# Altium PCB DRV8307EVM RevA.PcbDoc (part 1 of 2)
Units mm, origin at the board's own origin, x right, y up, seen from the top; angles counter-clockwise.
Board outline 87.73 x 75 mm, 2 copper layers (Top Layer, Bottom Layer), stack 1.575 mm thick; 84 components, 57 nets, 289 pads, 360 vias.
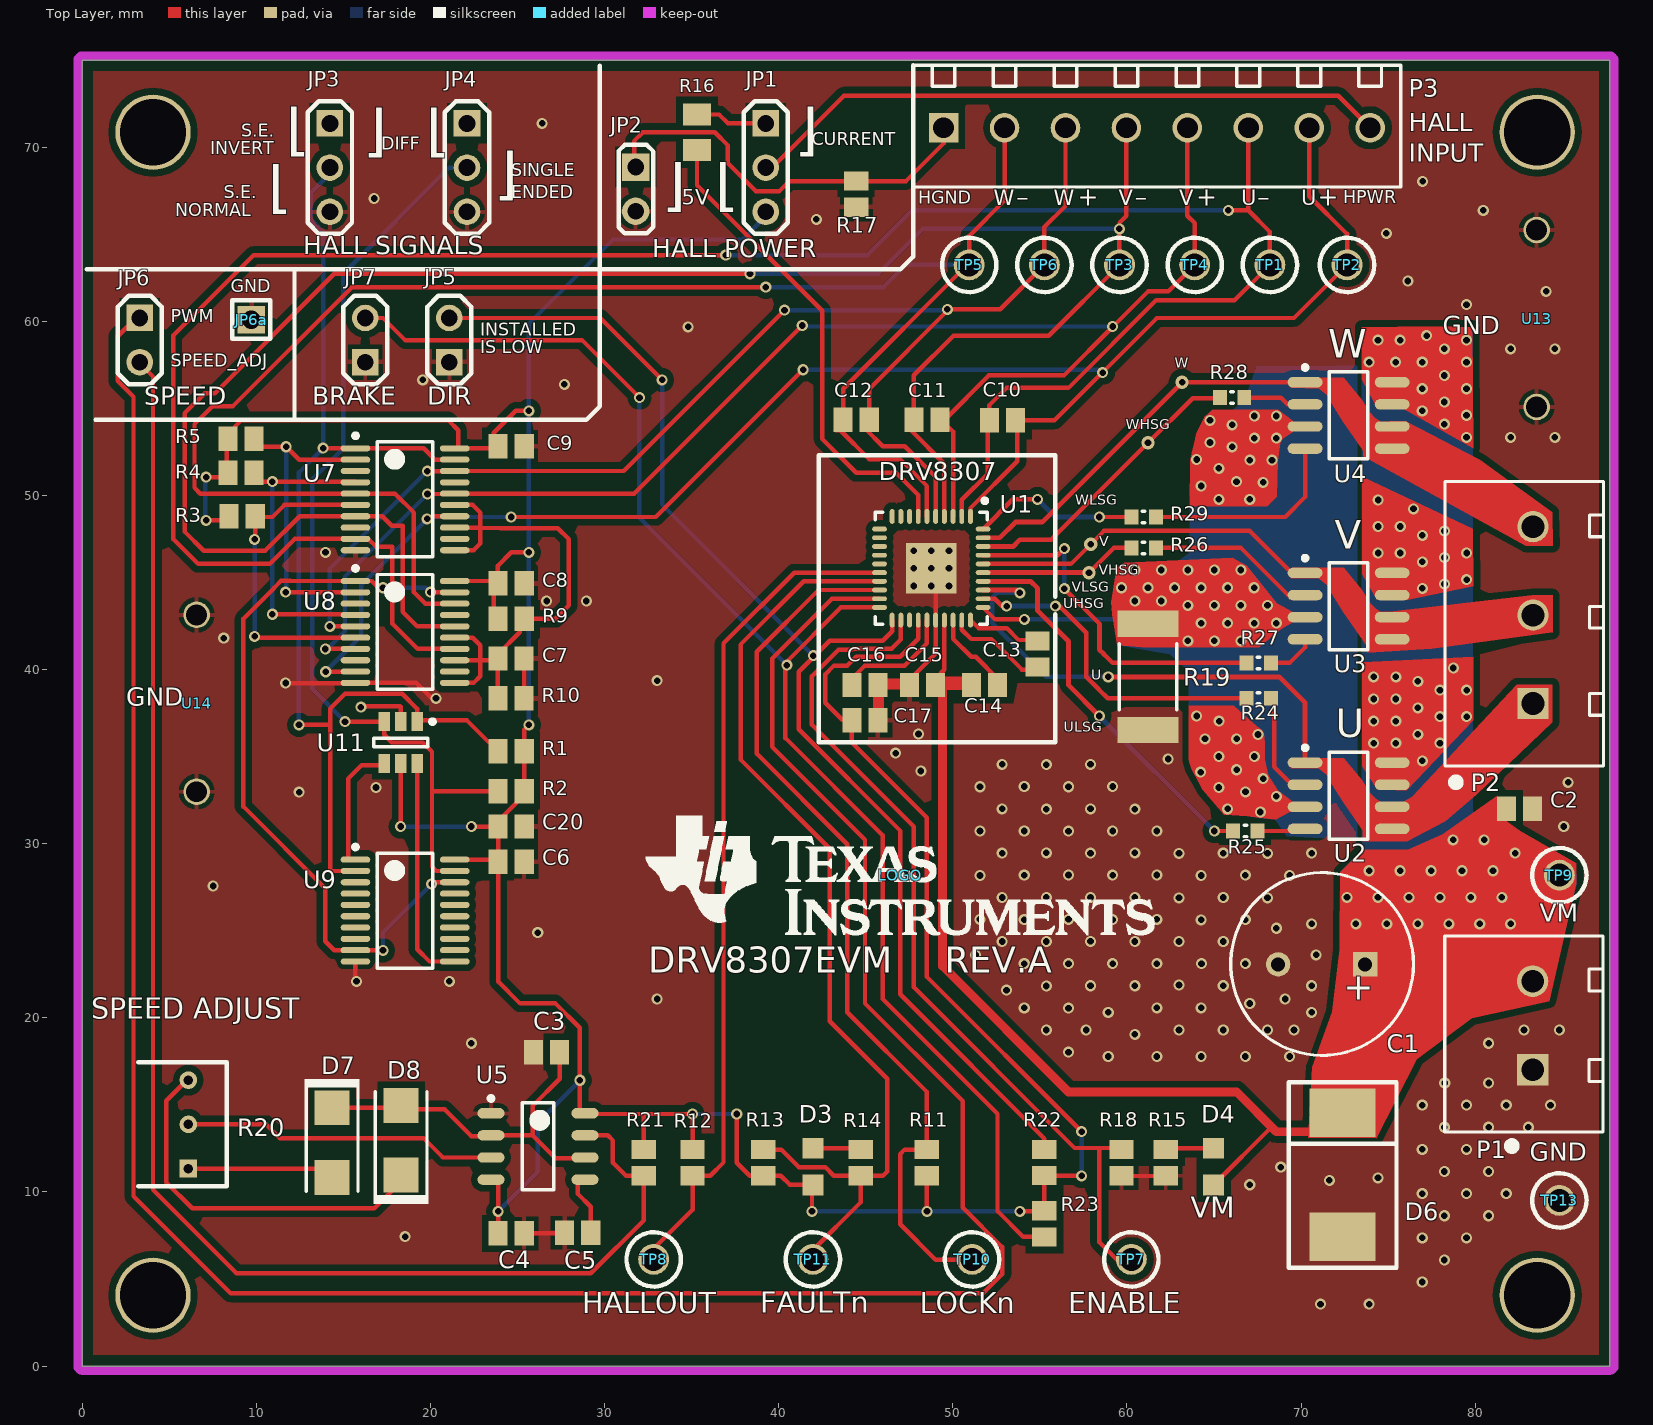
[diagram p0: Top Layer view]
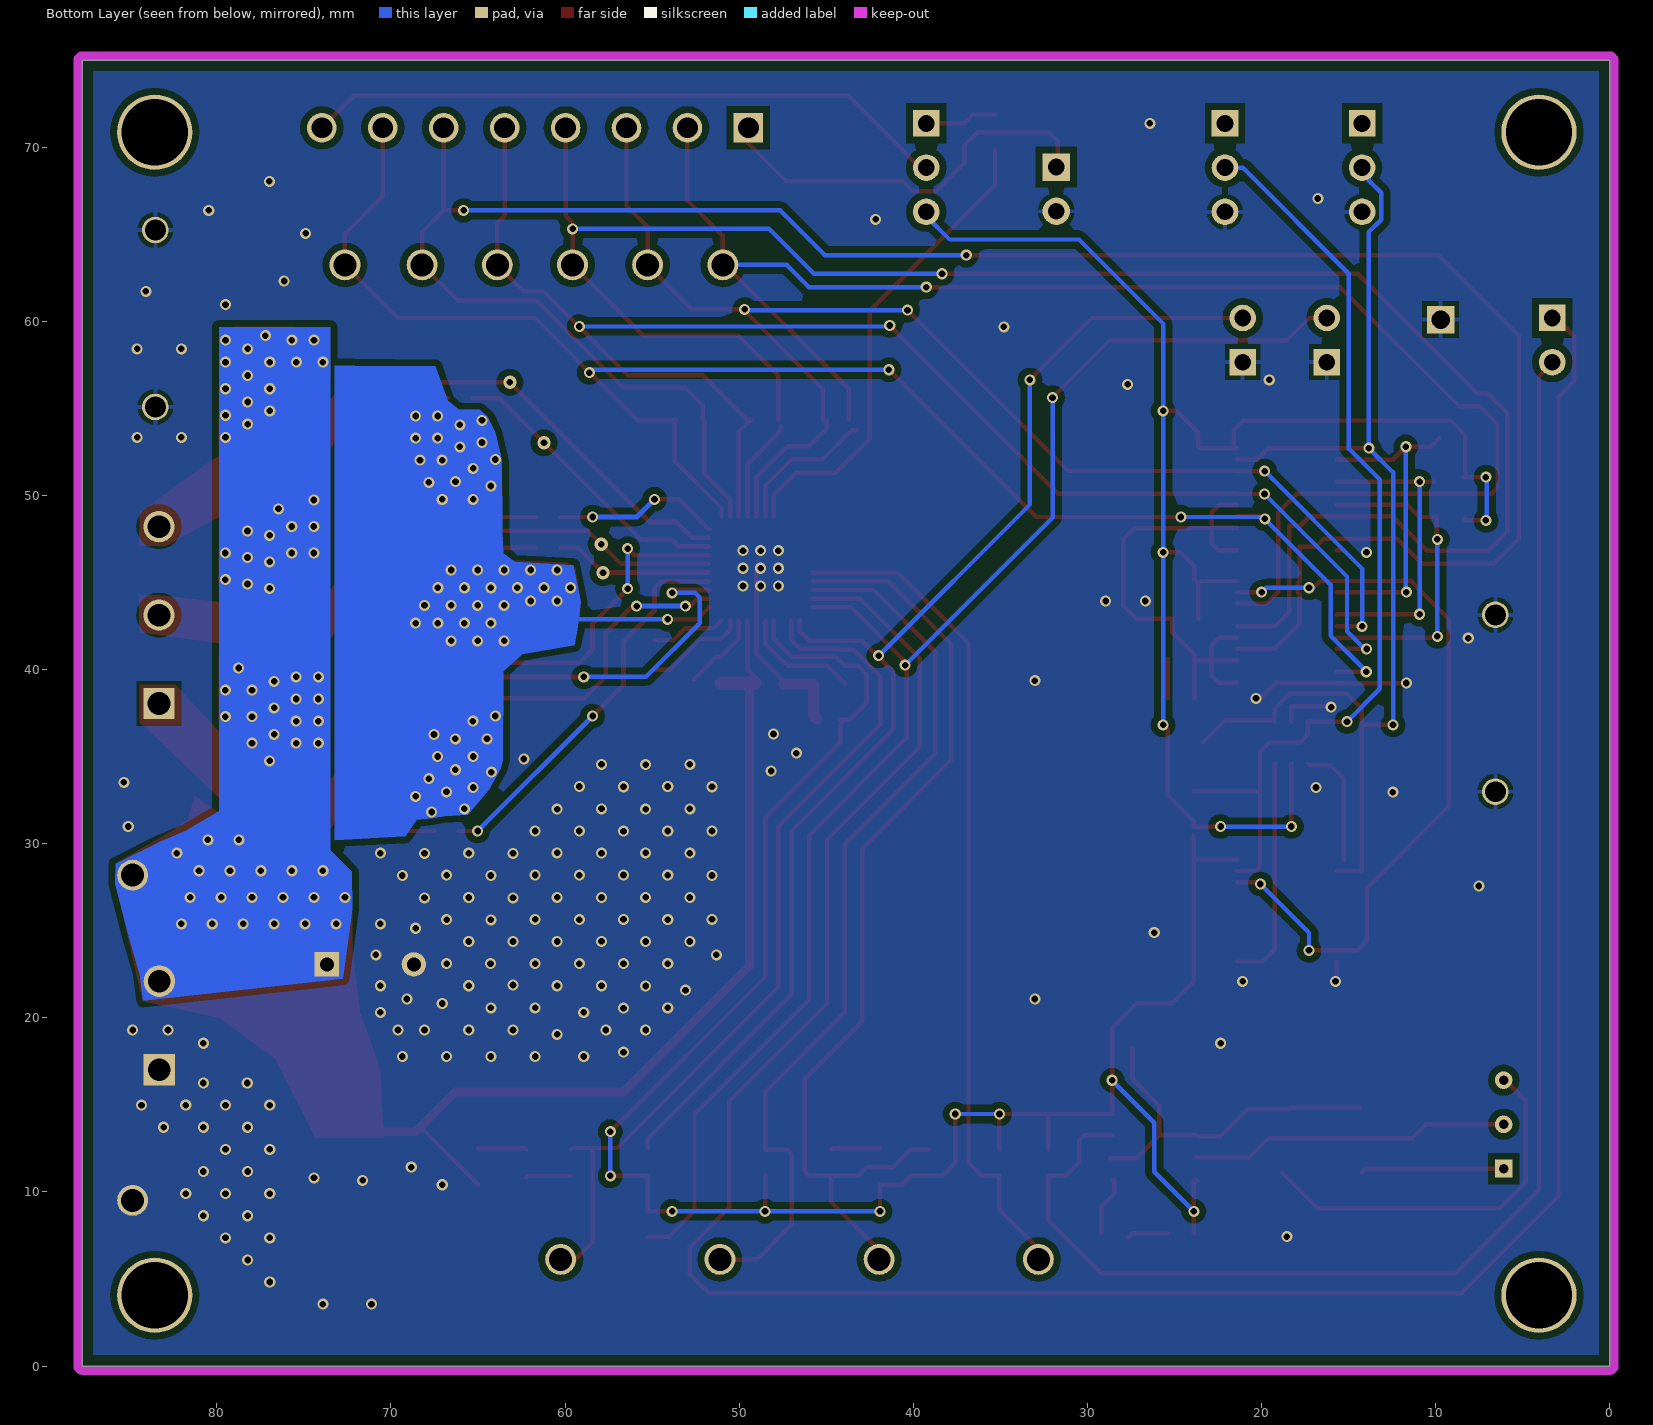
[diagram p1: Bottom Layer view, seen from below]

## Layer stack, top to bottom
Top Layer: signal copper 0.0356
Dielectric: core 1.5037, FR-4, Dk 4.8
Bottom Layer: signal copper 0.0356

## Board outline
0,0 0,75 87.732,75 87.732,0

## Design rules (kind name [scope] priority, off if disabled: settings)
AcuteAngle [All] p1: minimum=1.50000000000000E+0001 checktracksonly=FALSE
AssemblyTestPointUsage [All] p1: valid=2
Clearance Clearance_BoardEdge_MountingHoles [OnCopper and InComponentClass('Mounting Holes') vs IsKeepOut] p1: gap=1.016
Clearance Clearance_BoardEdge_Poly [OnCopper and InPoly vs IsKeepOut] p2: gap=0.635
Clearance Clearance_BoardEdge [OnCopper and Not InComponentClass('Logo') and not InComponentClass('FiducialMark') and not InRegion(1000,500,4000,800) and Not IsKeepout vs IsKeepOut] p3: gap=1.905
Clearance Clearance_Poly [InPolygon] p4: gap=0.381
Clearance [All] p5: gap=0.203
ComponentClearance ComponentClearance_Logo [InComponentClass('Logo')] p1: gap=1.27 collisioncheckmode=3 verticalgap=0.254 showdistances=FALSE
ComponentClearance ComponentClearance_ScrewToNut [(HasFootprint('NY PMS 440 0025 PH')) vs (HasFootprint('Keystone_1902C'))] p2: gap=0.127 collisioncheckmode=3 verticalgap=0.254 showdistances=FALSE
ComponentClearance ComponentClearance_MountingHoles [InComponentClass('Mounting Holes')] p3: gap=6.35 collisioncheckmode=3 verticalgap=2540 showdistances=FALSE
ComponentClearance ComponentClearance_SmallPassives [HasFootprint('0201*') or HasFootprint('0402*') or HasFootprint('0508') or HasFootprint('0603*') or HasFootprint('0612') or HasFootprint('0805*') or HasFootprint('0815*') or HasFootprint('0830*') or HasFootprint('1206*') or HasFootprint('1210*') or HasFootprint('1808*') or HasFootprint('1812*') or HasFootprint('1825*') or HasFootprint('2010*') or HasFootprint('2220*') or HasFootprint('2225*') or HasFootprint('2512*') or HasFootprint('2728*') or HasFootprint('3518*') vs HasFootprint('0201*') or HasFootprint('0402*') or HasFootprint('0508') or HasFootprint('0603*') or HasFootprint('0612') or HasFootprint('0805*') or HasFootprint('0815*') or HasFootprint('0830*') or HasFootprint('1206*') or HasFootprint('1210*') or HasFootprint('1808*') or HasFootprint('1812*') or HasFootprint('1825*') or HasFootprint('2010*') or HasFootprint('2220*') or HasFootprint('2225*') or HasFootprint('2512*') or HasFootprint('2728*') or HasFootprint('3518*')] p4: gap=0.508 collisioncheckmode=3 verticalgap=0.254 showdistances=FALSE
ComponentClearance ComponentClearance_THtoSMT [IsThruComponent vs IsSMTComponent] p5: gap=1.38 collisioncheckmode=3 verticalgap=0.762 showdistances=FALSE
ComponentClearance ComponentClearance_THtoTH [IsThruComponent vs IsThruComponent] p6: gap=0 collisioncheckmode=3 verticalgap=0.762 showdistances=FALSE
ComponentClearance [All] p7: gap=1.016 collisioncheckmode=3 verticalgap=0.254 showdistances=FALSE
DiffPairsRouting [All] p1: maxlimit=2.54 minlimit=0.254 mostfreqgap=0.254 maxuncoupledlength=25.4
FabricationTestPointUsage TestPointUsage [All] p1: valid=2 allowmultiple=FALSE
FabricationTestpoint Testpoint [All] p1: side=3 testpointundercomponent=TRUE minsize=1.016 maxsize=2.54 preferedsize=1.524 minholesize=0 maxholesize=1.016 preferedholesize=0.813 testpointgrid=0.025 allowsidetop=TRUE allowsidebottom=TRUE usegrid=TRUE gridtolerance=0
FanoutControl Fanout_LCC [IsLCC] p1: bgadir=Out bgaviamode=Centered fanoutstyle=Auto fanoutdirection=Alternating viagrid=0.025 // Fanout_LCC (Default Rule)
FanoutControl Fanout_BGA [IsBGA] p2: bgadir=Out bgaviamode=Centered fanoutstyle=Auto fanoutdirection=Alternating viagrid=0.025 // Fanout_BGA (Default Rule)
FanoutControl Fanout_Default [All] p4: bgadir=Out bgaviamode=Centered fanoutstyle=Auto fanoutdirection=Alternating viagrid=0.025 // Fanout_Default (Default Rule)
FanoutControl Fanout_Small [(CompPinCount < 5)] p5: bgadir=Out bgaviamode=Centered fanoutstyle=Auto fanoutdirection=OutThenIn viagrid=0.025 // Fanout_Small (Default Rule)
HoleSize [All] p1: absolutevalues=TRUE maxlimit=6.375 minlimit=0.203 maxpercent=80.000 minpercent=20.000
MinimumAnnularRing [All] p1: minimumring=0.127
MinimumSolderMaskSliver MinimumSolderMaskSliver_Logo [InComponentClass('Logo') vs InComponentClass('Logo')] p1: minsoldermaskwidth=0.018
MinimumSolderMaskSliver [All] p2: minsoldermaskwidth=0.076
PlaneConnect [All] p1: planeconnectstyle=Relief reliefexpansion=0.254 reliefentries=4 reliefconductorwidth=0.254 reliefairgap=0.254
PolygonConnect PolygonConnect_1 [IsNamedPolygon('Top GND plane') or IsNamedPolygon('Bottom GND plane') vs not ( InComponent('U1') or InComponent('C1') or       InComponent('C2') or InComponent('P1') or       InComponent('D6') or InComponent('R19') or       InComponent('TP13') or   InComponent('C3') or       InComponent('U11') or       IsStitchingVia or IsVia)] p1: connectstyle=Relief reliefconductorwidth=0.254 reliefentries=4 polygonreliefangle="90 Angle" airgapwidth=0.254
PolygonConnect [All] p2: connectstyle=Direct reliefconductorwidth=0.254 reliefentries=4 polygonreliefangle="90 Angle" airgapwidth=0.254
RoutingVias [All] p1: holewidth=0.406 width=0.864 viastyle="Through Hole" minholewidth=0.203 minwidth=0.635 maxholewidth=1.016 maxwidth=1.651
SMDToCorner [All] p1: distance=0
SilkToSilkClearance [All] p1: silktosilkclearance=0.076
SilkscreenOverComponentPads [All] p1: minsilkscreentomaskgap=0.051
SolderMaskExpansion [All] p1: expansion=0.076
Width [All] p1: maxlimit=2.54 minlimit=0.152 preferedwidth=0.254 checkconnectedcopper=TRUE
14 further rules are at their usual default settings.

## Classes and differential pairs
component class Logo: LOGO

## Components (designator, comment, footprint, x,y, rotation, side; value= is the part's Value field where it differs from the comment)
C1 "220uF" UVZ1J221MPD_fp 71.374,23.114 r180 top
C2 "06031C272JAT2A" 0805L 82.55,32.004 r0 top
C3 "GRM155R61A103KA01D" 0805L 26.67,18.034 r0 top
C4 "C1005X5R1A104K" 0805L 24.638,7.62 r180 top
C5 "GRM155R61A103KA01D" 0805L 28.454,7.662 r180 top
C6 "Cap" 0805L 24.638,28.956 r180 top
C7 "" 0805L 24.626,40.64 r0 top
C8 "Cap" 0805L 24.638,44.958 r180 top
C9 "Cap" 0805L 24.638,52.832 r180 top
C10 "C0805C104K5RACTU" 0805L 52.851,54.319 r180 top
C11 "C0805C104K5RACTU" 0805L 48.514,54.356 r180 top
C12 "C0805C104K5RACTU" 0805L 44.45,54.356 r180 top
C13 "C0805C104K5RACTU" 0805L 54.864,40.894 r90 top
C14 "C0805C104K5RACTU" 0805L 51.816,39.116 r0 top
C15 "C0805C104K5RACTU" 0805L 48.26,39.116 r180 top
C16 "C0805C104K5RACTU" 0805L 44.958,39.116 r180 top
C17 "C0805C104K5RACTU" 0805L 44.958,37.084 r180 top
C20 "" 0805L 24.638,30.988 r0 top
D3 "LTST-C170KRKT" LED_LTST-C170 41.964,11.459 r90 top
D4 "LTST-C171GKT" LED_LTST-C171 64.979,11.459 r90 top
D6 "1.5SMC33" SMC-W 72.385,7.433 r90 top
D7 "MBRA210LT3G" SMA 14.349,12.838 r270 top
D8 "MBRA210LT3G" SMA 18.313,12.971 r90 top
JP1 "JUMPER_3X100MIL" HDR100_1X3 39.255,71.374 r270 top
JP2 "JUMPER_2X100MIL" "2PIN HEADER" 30.568,70.016 r270 top
JP3 "JUMPER_3X100MIL" HDR100_1X3 14.224,71.374 r270 top
JP4 "JUMPER_3X100MIL" HDR100_1X3 22.098,71.374 r270 top
JP5 "" HDR100_1X2 21.082,57.658 r90 top
JP6 "" HDR100_1X2 3.302,60.198 r270 top
JP6a "PartNumber" "1x1 Header" 10.922,58.928 r90 top
JP7 "" HDR100_1X2 16.256,57.658 r90 top
LOGO "Texas Instruments" TI_Stacked_Overlay_Medium 46.99,28.194 r0 top
P1 "OSTTA024163" On-Shore_OSTTA024163 82.804,19.064 r90 top
P2 "OSTTA034163" On-Shore_OSTTA034163 82.823,42.632 r90 top
P3 "OSTTE080161" On-Shore_OSTTE080161 61.722,71.12 r0 top
R1 "" 0805L 24.638,35.306 r0 top
R2 "" 0805L 24.638,33.02 r0 top
R3 "" 0805L 9.184,48.819 r180 top
R4 "" 0805L 9.124,51.308 r180 top
R5 "" 0805L 9.124,53.269 r180 top
R9 "" 0805L 24.638,42.926 r180 top
R10 "RT0805BRD0710KL" 0805L 24.626,38.354 r180 top
R11 "30K" 0805l 48.514,11.684 r270 top
R12 "15K" 0805L 35.052,11.684 r90 top
R13 "30K" 0805L 39.116,11.684 r270 top
R14 "3K" 0805L 44.704,11.684 r90 top
R15 "Res1" 0805L 62.23,11.684 r90 top
R16 "ERJ-6GEYJ202V" 0805_HV 35.306,70.866 r90 top
R17 "CRCW0805180RJNEA" 0805L 44.45,67.31 r270 top
R18 "" 0805L 59.69,11.684 r90 top
R19 "PartNumber" 2512M 61.214,39.584 r90 top
R20 "3352T-1-502LF" 3352_Trimmer_Pot 6.096,13.886 r90 top
R21 "CRCW040210K0JNED" 0805L 32.258,11.684 r90 top
R22 "" 0805L 55.258,11.696 r270 top
R23 "" 0805L 55.258,8.168 r90 top
R24 "RC0603FR-07240RL" 0603L 67.564,38.354 r0 top
R25 "RC0603FR-07240RL" 0603L 66.802,30.734 r0 top
R26 "RC0603FR-07240RL" 0603L 60.96,46.99 r0 top
R27 "RC0603FR-07240RL" 0603L 67.564,40.386 r0 top
R28 "RC0603FR-07240RL" 0603L 66.04,55.626 r0 top
R29 "RC0603FR-07240RL" 0603L 60.96,48.768 r0 top
TP1 "TP-LOOP-ORANGE" "TEST POINT 0.052" 68.212,63.246 r0 top
TP2 "TP-LOOP-ORANGE" "TEST POINT 0.052" 72.644,63.246 r0 top
TP3 "TP-LOOP-ORANGE" "TEST POINT 0.052" 59.576,63.246 r0 top
TP4 "TP-LOOP-ORANGE" "TEST POINT 0.052" 63.894,63.246 r0 top
TP5 "TP-LOOP-ORANGE" "TEST POINT 0.052" 50.94,63.246 r0 top
TP6 "TP-LOOP-ORANGE" "TEST POINT 0.052" 55.258,63.246 r0 top
TP7 "TP-LOOP-ORANGE" "TEST POINT 0.052" 60.252,6.129 r0 top
TP8 "TP-LOOP-ORANGE" "TEST POINT 0.052" 32.82,6.129 r0 top
TP9 "TP-LOOP-ORANGE" "TEST POINT 0.052" 84.836,28.194 r0 top
TP10 "TP-LOOP-BLACK" "TEST POINT 0.052" 51.108,6.129 r0 top
TP11 "TP-LOOP-ORANGE" "TEST POINT 0.052" 41.964,6.129 r0 top
TP13 "TP-LOOP-BLACK" "TEST POINT 0.052" 84.836,9.517 r0 top
U1 "DRV8307" RHA0040A 48.766,45.822 r270 top
U2 "CSD88537ND" SO-8_N 72.734,32.757 r0 top
U3 "CSD88537ND" SO-8_N 72.734,43.648 r0 top
U4 "CSD88537ND" SO-8_N 72.734,54.601 r0 top
U5 "TLC555" SOIC127P600X175-8N 26.178,12.616 r0 top
U7 "SN74CBT3244CPW" PW0020A_N 18.542,49.784 r0 top
U8 "SN74CBT3244CPW" PW0020A_N 18.542,42.164 r0 top
U9 "SN74CBT3244CPW" PW0020A_N 18.542,26.162 r0 top
U11 "SN74LVC2G14DBVR" DBV0006A_N 18.288,35.814 r270 top
U13 "" GND_Bridge 81.534,53.086 r0 top
U14 "" GND_Bridge 4.572,30.988 r0 top

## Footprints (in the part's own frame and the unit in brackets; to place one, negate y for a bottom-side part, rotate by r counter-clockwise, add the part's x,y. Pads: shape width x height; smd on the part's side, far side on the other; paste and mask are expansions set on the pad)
"1x1 Header" [mil]
  rect 62x62 hole 42: 1(46.41,47.38)
  silkscreen extent 3,5 90,90
"2PIN HEADER" [mil]
  rect 62x62 hole 38: 1(45.31,48.03)
  round 62 hole 38: 2(145.31,48.03)
  silkscreen extent -5,9 195,88
0603L [mm] "0603 from SM-752 data"
  rect 0.8x0.85 smd: 1(-0.7,0) 2(0.7,0)
  silkscreen extent -0.07,-0.33 0.07,0.33, body extent -0.87,-0.47 0.87,0.47, height 0.85
0805_HV [mil] "0805 with 30mil clearance between pads"
  rect 50x63 smd: 1(-40,0) 2(40,0)
  body extent -43,-29 43,29, height 43
0805L [mm] "0805 from SM-752 data"
  rect 1.1x1.4 smd: 1(-0.75,0) 2(0.75,0)
  body extent -1.1,-0.72 1.1,0.72, height 1.1
0805l [mm] "0805 from SM-752 data"
  rect 1.1x1.4 smd: 1(-0.75,0) 2(0.75,0)
  body extent -1.1,-0.72 1.1,0.72, height 1.1
2512M [mm] "Chip Resistor, Body 6.3x3.2mm, IPC Low Density"
  rect 1.5x3.5 smd: 1(-3.05,0) 2(3.05,0)
  silkscreen extent -1.9,-1.65 1.9,1.65, body extent -3.22,-1.67 3.22,1.67, height 0.71
3352_Trimmer_Pot [mil]
  rect 40x40 hole 21.65: 1(-100,0)
  round 40 hole 21.65: 2(0,0) 3(100,0)
  silkscreen extent -140,-87 140,113
DBV0006A_N [mm] "SOT23, 6-Leads, Body 2.9x1.6mm, Pitch 0.95mm, Lead Span 2.8mm, IPC Medium Density"
  rect 1.1x0.65 smd: 1(-1.2,0.95) 2(-1.2,0) 3(-1.2,-0.95) 4(1.2,-0.95) 5(1.2,0) 6(1.2,0.95)
  silkscreen extent -1.32,-1.55 0.25,1.95, body extent -1.42,-1.46 1.42,1.46, height 1.11
GND_Bridge [mm] "Test Pin for GND"
  round 1.524 hole 1.2: 1(2,12.16) 2(2,2)
HDR100_1X2 [mil]
  rect 60x60 hole 38: 1(0,0)
  round 60 hole 38: 2(100,0)
  silkscreen extent -50,-50 150,50
HDR100_1X3 [mil]
  rect 60x60 hole 38: 1(0,0)
  round 60 hole 38: 2(100,0) 3(200,0)
  silkscreen extent -50,-50 250,50
LED_LTST-C170 [mm] "LITE-ON"
  rect 1.2x1.2 smd: 1(-1.05,0) 2(1.05,0)
  body extent -1.05,-0.67 1.05,0.67, height 1.1
LED_LTST-C171 [mm] "LITE-ON"
  rect 1.2x1.2 smd: 1(-1.05,0) 2(1.05,0)
  body extent -1.05,-0.67 1.05,0.67, height 0.8
On-Shore_OSTTA024163 [mm] "TERM BLOCK 2x1, 5.08mm, TH"
  rect 1.8x1.8 hole 1.3: 1(-2.04,-0.5)
  round 1.8 hole 1.3 paste+0: 2(3.04,-0.5)
  silkscreen extent -6.53,-4.55 5.63,4.55, body extent -5.68,-4.6 5.68,4.6, height 13
On-Shore_OSTTA034163 [mm] "TERM BLOCK 3x1, 5.08mm, TH"
  rect 1.8x1.8 hole 1.3: 1(-4.58,-0.5)
  round 1.8 hole 1.3 paste+0: 2(0.5,-0.5) 3(5.58,-0.5)
  silkscreen extent -9.2,-4.55 8.17,4.55, body extent -8.22,-4.6 8.22,4.6, height 13
On-Shore_OSTTE080161 [mm] "Term Blk 8x1"
  rect 1.7x1.7 hole 1.2: 1(-12.25,0)
  round 1.7 hole 1.2: 2(-8.75,0) 3(-5.25,0) 4(-1.75,0) 5(1.75,0) 6(5.25,0) 7(8.75,0) 8(12.25,0)
  silkscreen extent -14,-3.4 14,3.6, body extent -14,-3.4 14,3.6, height 8.4
PW0020A_N [mm] "TSOP, 20-Leads, Body 6.5x4.4mm, Pitch 0.65mm, IPC Medium Density"
  oval 1.7x0.35 smd: 1(-2.85,2.925) 2(-2.85,2.275) 3(-2.85,1.625) 4(-2.85,0.975) 5(-2.85,0.325) 6(-2.85,-0.325) 7(-2.85,-0.975) 8(-2.85,-1.625) 9(-2.85,-2.275) 10(-2.85,-2.925) 11(2.85,-2.925) 12(2.85,-2.275) 13(2.85,-1.625) 14(2.85,-0.975) 15(2.85,-0.325) 16(2.85,0.325) 17(2.85,0.975) 18(2.85,1.625) 19(2.85,2.275) 20(2.85,2.925)
  silkscreen extent -2.97,-3.3 1.6,3.77, body extent -2.25,-3.3 2.25,3.3, height 1.2
RHA0040A [mm] "QFN, 40-Leads, Body 6x6mm, Pitch 0.5mm, Thermal Pad 2.9x2.9mm, TI Recommended"
  oval 0.85x0.28 smd paste-0.025 mask+0.07: 1(-2.975,2.25) 2(-2.975,1.75) 3(-2.975,1.25) 4(-2.975,0.75) 5(-2.975,0.25) 6(-2.975,-0.25) 7(-2.975,-0.75) 8(-2.975,-1.25) 9(-2.975,-1.75) 10(-2.975,-2.25) 21(2.975,-2.25) 22(2.975,-1.75) 23(2.975,-1.25) 24(2.975,-0.75) 25(2.975,-0.25) 26(2.975,0.25) 27(2.975,0.75) 28(2.975,1.25) 29(2.975,1.75) 30(2.975,2.25)
  oval 0.28x0.85 smd paste-0.025 mask+0.07: 11(-2.25,-2.975) 12(-1.75,-2.975) 13(-1.25,-2.975) 14(-0.75,-2.975) 15(-0.25,-2.975) 16(0.25,-2.975) 17(0.75,-2.975) 18(1.25,-2.975) 19(1.75,-2.975) 20(2.25,-2.975) 31(2.25,2.975) 32(1.75,2.975) 33(1.25,2.975) 34(0.75,2.975) 35(0.25,2.975) 36(-0.25,2.975) 37(-0.75,2.975) 38(-1.25,2.975) 39(-1.75,2.975) 40(-2.25,2.975)
  rect 2.9x2.9 smd paste-2.45 mask+0.07: 41(0,0)
  silkscreen extent -4,-3.22 3.22,3.22, body extent -3.08,-3.08 3.08,3.08, height 1
SMA [mm] "Molded Diode, 2-Leads, Body 4.3x2.6mm, IPC Medium Density, based on OnSemi component dimensions and land pattern"
  rect 2x2 smd: 1(-2,0) 2(2,0)
  silkscreen extent -3.66,-1.57 2.79,1.57, body extent -2.6,-1.3 2.6,1.3, height 2.42
SMC-W [mil]
  rect 110x150 smd: 1(0,0) 2(280,0)
  silkscreen extent -70,-122 349,122
SO-8_N [mm] "SOIC, 8-Leads, Body 4.9x3.9mm, Pitch 1.27mm, IPC Medium Density"
  oval 2x0.6 smd: 1(-2.5,1.905) 2(-2.5,0.635) 3(-2.5,-0.635) 4(-2.5,-1.905) 5(2.5,-1.905) 6(2.5,-0.635) 7(2.5,0.635) 8(2.5,1.905)
  silkscreen extent -2.62,-2.5 1.1,2.88, body extent -2,-2.5 2,2.5, height 1.75
SOIC127P600X175-8N [mm] "SOIC, 8-Leads, Body 5.0x4.0mm (max), Pitch 1.27mm, IPC Medium Density"
  oval 1.55x0.6 smd: 1(-2.7,1.905) 2(-2.7,0.635) 3(-2.7,-0.635) 4(-2.7,-1.905) 5(2.7,-1.905) 6(2.7,-0.635) 7(2.7,0.635) 8(2.7,1.905)
  silkscreen extent -2.82,-2.5 0.9,2.88, body extent -3.01,-2.51 3,2.49, height 1.75
"TEST POINT 0.052" [mil] "Glass Beaded Test Point"
  round 70 hole 52: 1(0,0)
  silkscreen extent -61,-61 62,61
TI_Stacked_Overlay_Medium [mm]
  silkscreen extent -14.62,-3.44 14.62,3.42
UVZ1J221MPD_fp [mm] "220uF footprint"
  rect 1.4x1.4 hole 0.8: 1(-2.31,0.045)
  round 1.4 hole 0.8: 2(2.69,0.045)
  silkscreen extent -5.09,-5.23 5.41,5.27, body extent -5.02,-5.2 5.43,5.29, height 27.01

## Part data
C1: library part UVZ1J221MPD
C2: "CAP, CERM, 2700pF, 100V, +/-5%, X7R, 0603"
C3 C5: "CAP, CERM, 0.01uF, 10V, +/-10%, X5R, 0402"
C4: "CAP, CERM, 0.1uF, 10V, +/-10%, X5R, 0402"
C6 C8 C9: "Capacitor"
C7 C20: library part Cap, "Capacitor"
C10 C11 C12 C13 C14 C15 C16 C17: "CAP, CERM, 0.1uF, 50V, +/-10%, X7R, 0805"
D3: "LED, Red, SMD"
D4: "LED, Green, SMD"
D6: library part "D Schottky", "Schottky Diode"
D7 D8: "Diode, Schottky, 10V, 2A, SMA"
JP1 JP3 JP4: "Header, Male 3-pin, 100mil spacing,"
JP2: "Header, Male 2-pin, 100mil spacing,"
JP5 JP6 JP7: library part JUMPER_2X100MIL, "Header, Male 2-pin, 100mil spacing,"
JP6a: library part "1x1 Header", "1x1 Header"
LOGO: library part TI_Logo, "Texas Instrument Corporate Signature"
P1: "Terminal Block, 2x1, 5.08mm, TH"
P2: "Terminal Block, 3x1, 5.08 mm, TH"
P3: "Terminal Block, 8x1, 3.5mm, TH"
R1 R2 R3 R4 R5 R9 R11 R12 R13 R14 R18 R22 R23: library part Res1, "Resistor"
R10: "RES, 10.0k ohm, 0.1%, 0.125W, 0805"
R15: "Resistor"
R16: "RES, 2.0k ohm, 5%, 0.125W, 0805"
R17: "RES, 180 ohm, 5%, 0.125W, 0805"
R19: library part CSRN2512FK30L0, "RES, 0.03 ohm, 1%, 2W, 2512"
R20: library part POT_3352P, "Potentiometer, 3/8 Cermet, SingleTurn, Flat"
R21: "RES, 10k ohm, 5%, 0.063W, 0402"
R24 R25 R26 R27 R28 R29: "RES, 240 ohm, 1%, 0.1W, 0603"
TP1 TP2 TP3 TP4 TP5 TP6 TP7 TP8 TP9 TP10 TP11 TP13: library part "TEST POINT", "Glass Beaded Test Point"
U1: library part DRV8308
U2 U3 U4: library part FDS8949, "MOSFET N-CH DUAL 30V 3.5A SOP8"
U5: "IC OSC MONO TIMING 2.1MHZ 8-SOIC"
U11: library part SN74LVC2G14IDBVRQ1, "DUAL SCHMITT-TRIGGER INVERTER, DBV0006A"
U13 U14: library part GND_Bridge

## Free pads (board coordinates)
  round 4.318 hole 3.81: 0(4.064,4.064) 0(4.064,70.866) 0(83.566,4.064) 0(83.566,70.866)

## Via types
v1: diameter 0.635, hole 0.381, Top Layer to Bottom Layer, tented both sides, 350 vias
v2: diameter 0.635, hole 0.381, Top Layer to Bottom Layer, tented bottom, 5 vias
v3: diameter 0.762, hole 0.381, Top Layer to Bottom Layer, tented bottom, 4 vias
v4: diameter 0.635/0.635 (per signal layer), hole 0.381, Top Layer to Bottom Layer, tented both sides, 1 vias

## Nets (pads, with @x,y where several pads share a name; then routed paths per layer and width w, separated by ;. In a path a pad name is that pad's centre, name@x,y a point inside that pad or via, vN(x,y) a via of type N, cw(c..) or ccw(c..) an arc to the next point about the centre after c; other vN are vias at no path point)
2V: C7.1 R9.1 R10.2 U7.11 U7.13 U7.15 U8.11 U8.13 U8.15 | length 31.5
  Top Layer w0.254: U8.11@21.392,39.239 22.475,39.239 22.86,39.624 22.86,40.539 ; U8.13@21.392,40.539 22.86,40.539 ; U8.15@21.392,41.839 22.423,41.839 22.86,41.402 22.86,40.539 ; U7.11@21.392,46.859 22.475,46.859 22.86,47.244 22.86,48.133 ; U7.13@21.392,48.159 22.834,48.159 22.86,48.133 ; U7.15@21.392,49.459 22.423,49.459 22.86,49.022 22.86,48.133 ; R10.2@23.876,38.354 C7.1@23.876,40.64 ; 22.86,40.539 23.775,40.539 C7.1@23.876,40.64 ; 22.86,48.133 24.003,48.133 24.016,48.12 27.318,48.12 27.94,47.498 27.94,43.688 27.178,42.926 25.134,42.926 25.134,42.152 23.876,40.894 C7.1@23.876,40.64
BRAKE: JP7.2 R23.1 U1.20 | length 83.1
  Top Layer w0.254: JP7.2@16.256,60.198 17.272,60.198 18.542,58.928 28.702,58.928 v1(32.004,55.626) ; U1.20@45.791,43.572 43.572,43.572 40.386,40.386 40.386,36.068 45.974,30.48 45.974,21.082 52.566,14.49 52.566,8.902 54.05,7.418 R23.1@55.258,7.418
  Bottom Layer w0.254: v1@31.995,55.626 31.995,48.738 v1(40.47,40.262)
CP1: C13.2 U1.30 | length 4.3
  Top Layer w0.254: U1.30@51.016,42.847 51.477,42.386 53.092,42.386 53.773,41.704 C13.2@54.87,41.704
CP2: C13.1 U1.29 | length 5.9
  Top Layer w0.254: U1.29@50.516,42.847 50.516,42.294 51.052,41.758 52.218,41.758 53.972,40.004 C13.1@54.87,40.004
DIR: JP5.2 R22.1 U1.21 | length 73.3
  Top Layer w0.254: JP5.2@21.082,60.198 29.747,60.198 v1(33.303,56.642) ; U1.21@46.516,42.847 46.516,42.198 45.974,41.656 44.069,41.656 42.926,41.656 41.148,39.878 41.148,36.576 46.99,30.734 46.99,21.352 ; 46.974,21.352 55.258,13.068 R22.1@55.258,12.533
  Bottom Layer w0.254: v1(33.303,56.642) 33.303,49.487 v1(41.989,40.801)
ENABLE#: R18.2 TP7.1 U1.22 | length 50.3
  Top Layer w0.254: U1.22@47.016,42.847 47.016,41.733 46.482,41.199 44.258,41.199 44.207,41.148 43.434,41.148 41.91,39.624 41.91,36.83 47.752,30.988 47.752,21.767 56.993,12.526 59.598,12.526 R18.2@59.69,12.434 ; 58.42,12.434 58.42,7.112 TP7.1@59.69,5.842
FAULTN: R13.1 R14.1 TP11.1 U1.17 | length 57
  Top Layer w0.254: R13.1@39.116,12.434 40.144,12.434 41.148,11.43 42.672,11.43 43.168,10.934 R14.1@44.704,10.934 ; TP11.1@41.964,6.129 41.964,6.658 44.704,9.398 R14.1@44.704,10.934 ; U1.17@45.791,45.072 41.445,45.072 37.81,41.438 37.81,34.834 42.926,29.718 42.926,19.812 46.228,16.51 46.228,11.176 45.986,10.934 R14.1@44.704,10.934
GND: C1.2 C2.2 C3.1 C4.1 C5.2 C6.1 C7.2 C8.1 C9.1 C15.2 C16.1 C17.1 C20.2 D6.1 JP2.2 JP3.3 JP4.3 JP5.1 JP6a.1 JP7.1 P1.1 R10.1 R15.1 R17.2 R18.1 R19.1 TP13.1 U1.26 U1.41 U5.1 U7.10 U8.10 U9.10 U11.2 U13.1 U13.2 U14.1 U14.2 | length 31.7
  Top Layer w0.254: v1(11.684,39.23) 15.683,39.23 U8.10@15.692,39.239 19.181,39.239 20.066,38.354 v1(20.32,38.354) ; U7.10@15.279,46.859 U7.10@15.692,46.859 ; U9.10@15.692,23.237 15.692,22.154 v1(15.748,22.098) ; v1(16.002,37.846) 16.05,37.894 18.252,37.894 18.288,37.858 U11.2@18.288,37.014 ; R10.1@25.376,38.354 C7.2@25.376,40.64 ; C4.1@25.388,7.62 27.432,7.62 C5.2@27.686,7.366 ; C15.2@47.458,39.363 49.016,40.921 U1.26@49.016,42.847 U1.41@49.016,45.572 ; R18.1@59.69,10.918 62.146,10.918 R15.1@62.23,10.834
  Top Layer w0.635: C17.1@45.552,37.152 45.72,37.321 45.72,39.184 C15.2@47.458,39.184
  other v1: 71.12,3.556 73.914,3.556 76.962,4.826 78.232,6.096 76.962,7.366 79.502,7.366 18.542,7.438 78.232,8.636 80.772,8.636 76.962,9.906 79.502,9.906 81.788,9.906 67.056,10.414 71.628,10.668 74.422,10.807 78.232,11.176 80.772,11.176 68.834,11.43 76.962,12.446 79.502,12.446 78.232,13.716 80.772,13.716 83.058,13.716 76.962,14.986 79.502,14.986 81.788,14.986 84.328,14.986 78.254,16.256 80.772,16.256 58.928,17.78 61.722,17.78 64.262,17.78 66.802,17.78 69.342,17.78 56.642,18.034 22.352,18.542 80.772,18.542 60.452,19.05 55.372,19.304 57.658,19.304 62.992,19.304 65.532,19.304 68.072,19.304 69.596,19.304 82.804,19.304 84.836,19.304 58.928,20.32 70.612,20.32 56.642,20.56 54.102,20.574 61.722,20.574 64.262,20.574 67.056,20.828 33.02,21.082 69.088,21.082 53.086,21.59 55.372,21.83 57.912,21.844 60.452,21.844 65.532,21.844 70.612,21.844 62.992,21.886 21.082,22.098 54.102,23.114 56.642,23.114 59.182,23.114 61.722,23.114 64.284,23.114 66.802,23.114 51.308,23.622 70.866,23.622 52.832,24.384 55.372,24.384 60.452,24.384 62.992,24.384 65.532,24.384 57.912,24.398 26.162,24.892 68.58,25.146 70.612,25.4 54.102,25.64 59.182,25.64 64.262,25.626 66.802,25.64 51.562,25.654 56.642,25.654 61.722,25.654 52.832,26.91 57.912,26.91 62.992,26.896 65.532,26.91 68.072,26.896 55.372,26.924 60.452,26.924 7.522,27.57 51.562,28.18 64.262,28.18 69.342,28.18 54.102,28.194 59.182,28.194 66.802,28.194 56.642,28.208 61.722,28.208 62.992,29.45 68.072,29.45 52.832,29.464 57.912,29.464 65.532,29.464 70.612,29.464 55.372,29.478 60.452,29.478 56.642,30.72 51.562,30.734 54.102,30.734 59.182,30.734 61.722,30.734 85.09,30.988 55.372,31.99 60.452,31.99 52.832,32.004 57.912,32.004 12.457,32.964 16.872,33.234 51.562,33.274 56.642,33.274 54.102,33.288 59.182,33.288 85.344,33.528 48.163,34.18 55.372,34.544 52.832,34.558 57.912,34.558 62.367,34.866 46.715,35.208 48.027,36.301 33.02,39.37 8.127,41.809 26.67,43.942 28.956,43.942 47.75,44.806 48.766,44.806 49.782,44.806 47.75,45.822 48.766,45.822 49.782,45.822 13.97,46.736 47.75,46.838 48.766,46.838 49.782,46.838 82.042,53.34 84.582,53.34 27.686,56.388 19.558,56.642 82.042,58.42 84.582,58.42 34.798,59.69 79.502,60.96 84.074,61.722 76.132,62.321 74.903,65.056 42.164,65.86 80.465,66.378 16.764,67.056 76.984,68.041 26.416,71.374
HALLOUT: R12.1 TP8.1 U1.16 | length 48.2
  Top Layer w0.254: TP8.1@33.02,6.096 33.02,6.95 35.052,8.982 R12.1@35.052,10.934 36.068,10.934 36.83,11.696 36.83,41.508 40.894,45.572 U1.16@45.791,45.572
HGND: JP2.1 P3.1 R17.1 | length 23.9
  Top Layer w0.254: JP2.1@31.696,68.445 31.696,70.358 32.204,70.866 36.322,70.866 37.084,70.104 37.084,69.088 38.684,67.488 40.043,67.488 40.615,68.06 R17.1@44.45,68.06 47.312,68.06 49.472,70.22 P3.1@49.472,71.12
HPWR: JP1.2 P3.8 | length 37.7
  Top Layer w0.254: JP1.2@38.862,68.58 39.37,68.58 43.746,72.956 72.136,72.956 P3.8@73.972,71.12
HU+: C10.1 P3.7 TP2.1 U1.1 U7.14 U8.9 | length 95
  Top Layer w0.254: v1(13.986,39.877) 15.68,39.877 U8.9@15.692,39.889 ; v1(19.812,48.657) 19.99,48.657 20.142,48.809 U7.14@21.392,48.809 ; v1(24.638,48.768) 32.945,48.768 v1(41.401,57.224) ; U1.1@51.016,48.797 51.016,49.284 53.701,51.969 C10.1@53.701,54.319 ; C10.1@53.601,54.319 C10.1@53.701,54.319 ; P3.7@70.472,71.12 70.472,67.196 72.644,65.024 TP2.1@72.644,63.246 69.596,60.198 61.722,60.198 55.843,54.319 C10.1@53.701,54.319
  Bottom Layer w0.254: 14.22,40.136 16.035,41.95 16.035,44.88 v1(19.812,48.657) 19.923,48.768 v1(24.638,48.768) ; v1(41.401,57.224) 58.444,57.224 v1(58.609,57.059) ; TP2.1@72.276,63.246 TP2.1@72.53,63.246
HU-: C10.2 P3.6 TP1.1 U1.2 U7.9 U8.14 | length 133.8
  Top Layer w0.254: 16.872,47.068 16.431,47.509 U7.9@15.692,47.509 12.203,47.509 10.766,46.072 6.657,46.072 5.231,47.498 5.231,59.195 9.84,63.804 v1@36.974,63.804 ; 16.879,47.062 17.815,47.062 17.815,45.077 17.92,44.972 17.92,44.436 17.815,44.331 17.815,42.637 19.263,41.189 U8.14@21.392,41.189 ; U1.2@50.516,48.797 50.516,49.754 52.001,51.239 C10.2@52.001,54.219 ; C10.2@52.101,54.319 52.101,55.195 53.086,56.179 56.642,56.179 61.677,61.214 ; 61.722,61.214 66.18,61.214 TP1.1@68.212,63.246 68.212,65.138 66.972,66.378 ; v1@65.837,66.378 66.972,66.378 ; P3.6@66.972,71.12 66.972,66.378
  Bottom Layer w0.254: v1(36.958,63.804) 45.078,63.804 47.652,66.378 v1@65.837,66.378
  other v1: 65.825,66.378
HV+: C11.1 P3.5 TP4.1 U1.3 U7.16 U8.7 | length 89
  Top Layer w0.254: v1(13.964,41.189) U8.7@15.692,41.189 ; v1(19.829,50.086) 21.369,50.086 U7.16@21.392,50.109 31.696,50.109 v1(41.353,59.766) ; C11.1@49.264,54.356 C11.1@49.335,54.356 ; C11.1@49.299,54.391 C11.1@49.335,54.356 ; U1.3@50.016,48.797 50.016,53.675 C11.1@49.335,54.356 ; 52.071,56.895 49.531,54.356 C11.1@49.335,54.356 ; 52.071,56.896 56.388,56.896 v1@59.192,59.7 ; v1(59.182,59.709) 59.201,59.709 61.214,61.722 62.37,61.722 TP4.1@63.894,63.246 63.894,65.646 63.472,66.068 P3.5@63.472,71.12
  Bottom Layer w0.254: v1(13.964,41.189) 13.954,41.199 14.084,41.199 15.091,42.206 15.091,45.348 v1(19.829,50.086) ; v1(41.353,59.766) 41.353,59.609 41.454,59.709 v1(59.182,59.709)
HV-: C11.2 P3.4 TP3.1 U1.4 U7.7 U8.16 | length 118.1
  Top Layer w0.254: U8.16@21.392,42.489 19.233,42.489 18.397,43.325 18.397,48.26 17.78,48.26 17.231,48.809 U7.7@15.692,48.809 12.487,48.809 10.516,46.838 10.179,46.838 10.174,46.833 6.975,46.833 5.878,47.93 5.878,54.719 7.039,55.88 7.62,55.88 14.478,62.738 v1(38.354,62.738) ; C11.2@47.599,53.986 47.599,53.747 49.516,51.83 U1.4@49.516,48.797 ; C11.2@47.764,54.356 47.764,56.908 50.038,59.182 55.512,59.182 TP3.1@59.576,63.246 59.564,63.258 v1(59.564,65.317) ; v1@59.576,65.317 59.576,65.672 59.972,66.068 P3.4@59.972,71.12
  Bottom Layer w0.254: v1@38.428,62.738 45.708,62.738 48.287,65.317 v1(59.564,65.317)
HW+: C12.1 P3.3 TP6.1 U1.5 U7.18 U8.5 | length 77.4
  Top Layer w0.254: v1(14.224,42.489) U8.5@15.692,42.489 ; v1(19.821,51.404) U7.18@21.387,51.404 ; U7.18@21.392,51.409 31.099,51.409 v1(40.335,60.645) ; C12.1@44.981,54.319 44.981,53.825 45.974,52.832 47.244,52.832 49.016,51.06 U1.5@49.016,48.797 ; C12.1@45.2,54.356 45.2,56.122 v1@49.727,60.649 ; v1@49.784,60.706 52.718,60.706 TP6.1@55.258,63.246 55.258,65.418 56.472,66.632 P3.3@56.472,71.12
  Bottom Layer w0.254: v1(14.224,42.489) 14.224,45.806 v1(19.821,51.404) ; v1(40.335,60.645) 49.643,60.645 v1(49.687,60.689)
HW-: C12.2 P3.2 TP5.1 U1.6 U7.5 U8.18 | length 101.3
  Top Layer w0.254: U8.18@21.392,43.789 19.711,43.789 19.05,44.45 19.05,49.022 17.963,50.109 U7.5@15.692,50.109 6.78,50.109 6.448,50.441 6.448,54.102 7.464,55.118 8.636,55.118 15.487,61.969 v1(39.255,61.969) ; C12.2@43.281,53.747 43.535,53.747 45.212,52.07 46.99,52.07 48.516,50.544 U1.6@48.516,48.797 ; C12.2@43.7,54.356 43.7,56.132 50.814,63.246 TP5.1@50.94,63.246 50.94,64.91 52.972,66.942 P3.2@52.972,71.12
  Bottom Layer w0.254: v1(39.255,61.969) 45.995,61.969 47.271,63.246 TP5.1@50.94,63.246
ISENSE: R19.2 U1.31 U2.3 U3.3 U4.3 | length 9
  Top Layer w0.254: U1.31@51.741,43.572 52.427,42.886 v1(54.108,42.886)
  Bottom Layer w0.254: v1(54.108,42.886) 60.471,42.886
  other v1: 67.661,31.823 65.786,32.004 68.586,32.726 66.808,32.98 65.284,33.234 67.824,33.742 64.231,34.113 66.3,34.25 65.284,35.012 67.316,35.012 64.485,36.028 66.3,36.028 67.528,36.274 65.297,37.044 64.008,37.338 63.5,41.656 65.024,41.656 66.548,41.656 64.262,42.672 65.786,42.672 67.31,42.672 68.58,42.672 63.5,43.688 65.024,43.688 66.548,43.688 68.072,43.688 60.452,43.942 61.976,43.942 59.69,44.704 61.214,44.704 62.738,44.704 64.262,44.704 65.786,44.704 67.31,44.704 60.452,45.72 61.976,45.72 63.5,45.72 65.024,45.72 66.548,45.72 65.278,49.784 67.056,49.784 64.262,50.546 67.824,50.76 66.294,50.8 65.278,51.562 67.062,52.03 68.332,52.03 64.008,52.07 66.046,52.792 64.776,53.046 67.316,53.3 68.586,53.3 66.046,54.062 64.776,54.316 67.316,54.57 68.586,54.57
LOCKN: R11.1 TP10.1 U1.18 | length 51.8
  Top Layer w0.254: U1.18@45.791,44.572 42.286,44.572 38.735,41.021 38.735,35.179 43.942,29.972 43.942,20.32 48.514,15.748 R11.1@48.514,12.434 47.232,12.434 46.974,12.176 46.974,8.146 49.024,6.096 51.074,6.096 TP10.1@51.108,6.129
NetC5_1: C5.1 U5.5 | length 3.6
  Top Layer w0.254: U5.5@28.402,10.547 U5.5@28.448,10.593 ; U5.5@28.448,10.668 U5.5@28.448,10.593 ; U5.5@28.565,10.711 U5.5@28.448,10.593 ; C5.1@29.204,7.662 29.204,9.15 28.448,9.906 U5.5@28.448,10.593
NetD3_2: D3.2 R14.2 | length 2.8
  Top Layer w0.254: D3.2@41.91,12.509 44.629,12.509 R14.2@44.704,12.434
NetD4_2: D4.2 R15.2 | length 2.8
  Top Layer w0.254: R15.2@62.23,12.446 62.293,12.509 D4.2@64.979,12.509
NetD7_2: D7.2 R20.1 | length 7.7
  Top Layer w0.254: 6.62,11.346 14.018,11.346 D7.2@14.24,11.124
NetD8_1: D8.1 R20.3 | length 21.9
  Top Layer w0.254: R20.3@6.096,16.51 4.826,15.24 4.826,10.547 6.313,9.06 16.78,9.06 18.812,11.092 D8.1@18.812,11.096
NetJP1_1: JP1.1 R16.2 | length 4.2
  Top Layer w0.254: R16.2@35.306,71.882 36.576,71.882 37.084,71.374 JP1.1@39.255,71.374
NetJP3_2: JP3.2 R1.1 U7.1 U7.19 U9.2 U11.1 | length 64.5
  Top Layer w0.254: v1(12.446,36.83) 14.235,36.83 ; v1@13.846,52.709 U7.1@15.692,52.709 19.612,52.709 20.262,52.059 U7.19@21.392,52.059 ; U9.2@15.692,28.437 14.235,28.437 14.235,36.83 ; U11.1@19.233,37.298 19.233,37.755 18.38,38.608 15.091,38.608 14.235,37.752 14.235,36.83 ; U11.1@19.238,37.014 19.308,37.084 22.098,37.084 R1.1@23.368,35.814
  Bottom Layer w0.254: v1(12.446,36.83) 12.446,51.328 v1(13.837,52.719) 13.837,65.137 13.132,65.842 13.132,67.386 13.837,68.091 13.837,68.447 JP3.2@14.224,68.834
NetJP4_2: JP4.2 R2.1 U9.19 U11.3 | length 54.8
  Top Layer w0.254: v1(15.091,37.014) U11.3@17.338,37.014 17.338,36.256 17.78,35.814 19.558,35.814 20.088,35.284 20.088,33.02 ; U9.19@21.392,28.437 20.331,28.437 20.088,28.68 20.088,33.02 ; R2.1@23.888,33.02 20.088,33.02
  Bottom Layer w0.254: v1(15.091,37.014) 13.208,38.897 13.208,50.918 14.986,52.696 14.986,62.738 21.082,68.834 JP4.2@22.098,68.834
NetR3_1: R3.1 U7.6 U8.6 | length 18.5
  Top Layer w0.254: v1@9.906,41.839 U8.6@15.692,41.839 ; v1(9.906,47.481) 9.934,47.509 R3.1@9.934,48.819 ; R3.1@10.16,48.768 10.922,48.768 11.613,49.459 U7.6@15.692,49.459
  Bottom Layer w0.254: v1(9.906,41.91) v1(9.906,47.481)
NetR4_1: R4.1 U7.4 U8.4 | length 17.8
  Top Layer w0.254: R4.1@10.077,50.8 U7.4@15.692,50.8 ; v1(10.922,43.18) 15.651,43.18 U8.4@15.692,43.139
  Bottom Layer w0.254: v1(10.922,43.18) v1@10.922,50.546
  other v1: 10.922,50.8
NetR5_1: R5.1 U7.2 U8.2 | length 18.8
  Top Layer w0.254: R5.1@9.811,53.28 10.288,52.802 v1(11.714,52.802) 12.457,52.059 U7.2@15.692,52.059 ; v1@11.684,44.439 U8.2@15.692,44.439
  Bottom Layer w0.254: v1(11.684,44.45) 11.714,44.48 v1(11.714,52.802)
NetR20_2: R20.2 U5.3 | length 18.5
  Top Layer w0.254: R20.2@6.096,13.886 10.557,13.886 11.347,13.096 19.602,13.096 20.717,11.981 U5.3@23.765,11.981
NetR24_2: R24.2 U2.2 | length 6.2
  Top Layer w0.254: R24.2@68.264,38.354 68.451,38.167 68.451,34.419 69.478,33.392 U2.2@70.234,33.392
NetR25_2: R25.2 U2.4 | length 2.8
  Top Layer w0.254: R25.2@67.502,30.734 70.116,30.734 U2.4@70.234,30.852
NetR26_2: R26.2 U3.2 | length 9.7
  Top Layer w0.254: R26.2@61.66,46.99 66.548,46.99 69.255,44.283 U3.2@70.234,44.283
NetR27_2: R27.2 U3.4 | length 2.8
  Top Layer w0.254: R27.2@68.264,40.386 69.342,40.386 70.234,41.278 U3.4@70.234,41.743
NetR28_2: R28.2 U4.2 | length 3.7
  Top Layer w0.254: R28.2@66.74,55.626 68.834,55.626 69.224,55.236 U4.2@70.234,55.236
NetR29_2: R29.2 U4.4 | length 11.8
  Top Layer w0.254: R29.2@61.66,48.768 69.088,48.768 70.234,49.914 U4.4@70.234,52.696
